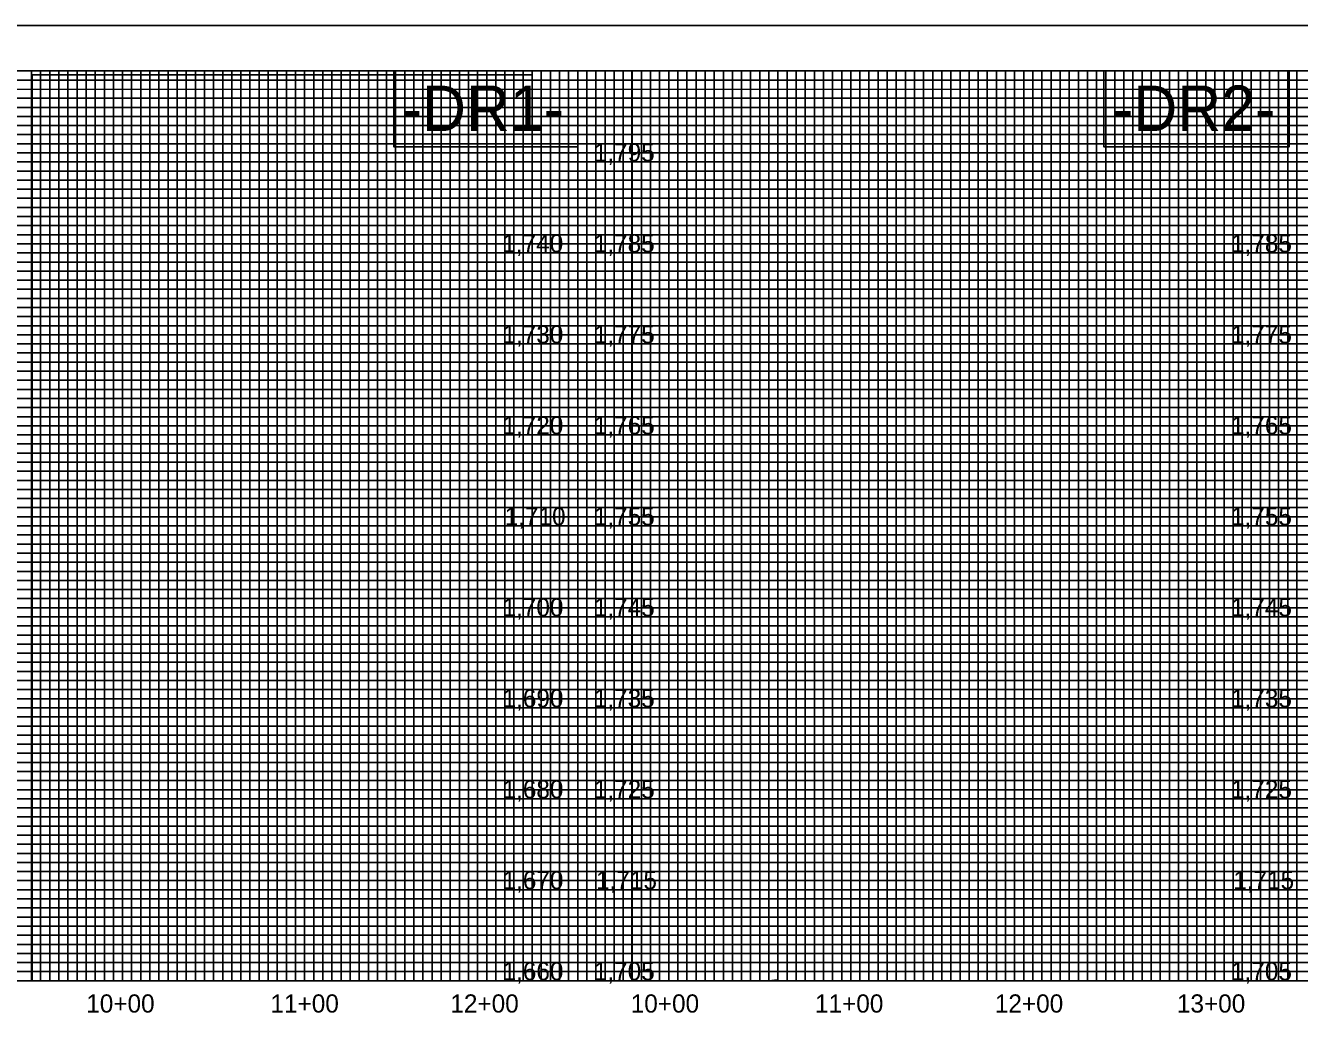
# Model space of a CAD drawing. Extents: x 505602 to 507286, y 483109 to 484209.
# Drawn here: x 506216 to 506916, y 483662 to 484209 of the extents above; entities that cross this region are included whole.
import ezdxf

# ---------------------------------------------------------------- set-up
doc = ezdxf.new("R2010")
doc.units = 0
for name, color, linetype in [('Exist Vertical Profile Vertical Axis Label', 7, 'Continuous'), ('Old_Level_1', 7, 'Continuous'), ('Prop Grid Mask', 7, 'Continuous'), ('Sheet Layout Profile Border Port 1', 7, 'Continuous'), ('Sheet Layout Profile Border Port 2', 7, 'Continuous'), ('Sheet Plot Border Outside CELL', 7, 'Continuous'), ('Sheet Profile CELL', 7, 'Continuous'), ('Sheet Profile Grid Major CELL', 7, 'Continuous'), ('Sheet Profile Grid Middle CELL', 7, 'Continuous'), ('Sheet Profile Grid Minor CELL', 7, 'Continuous')]:
    doc.layers.add(name, color=color, linetype=linetype)

msp = doc.modelspace()

# ---------------------------------------------------------------- linework, layer by layer
at = {"layer": 'Prop Grid Mask'}
for points in [[(506519.08, 484183.71), (506418.09, 484183.71), (506418.09, 484142), (506519.08, 484142)], [(506909.78, 484183.71), (506808.15, 484183.71), (506808.15, 484142), (506909.78, 484142)]]:
    msp.add_lwpolyline(points, close=True, dxfattribs=at)
at = {"layer": 'Sheet Layout Profile Border Port 1'}
msp.add_lwpolyline([(506219.48, 484181.62), (506494.08, 484181.62), (506494.08, 483683.71), (506219.48, 483683.71)], close=True, dxfattribs=at)
at = {"layer": 'Sheet Layout Profile Border Port 2'}
for points in [[(506519.08, 484183.71), (506869.08, 484183.71), (506869.08, 483683.71), (506519.08, 483683.71)], [(506548.8, 484183.71), (506869.08, 484183.71), (506869.08, 483683.71), (506548.8, 483683.71)]]:
    msp.add_lwpolyline(points, close=True, dxfattribs=at)
at = {"layer": 'Sheet Plot Border Outside CELL'}
msp.add_lwpolyline([(505602.08, 483108.71), (507286.08, 483108.71), (507286.08, 484208.71), (505602.08, 484208.71)], close=True, dxfattribs=at)
at = {"layer": 'Sheet Profile CELL'}
for p, q in [((506519.08, 483683.71), (506519.08, 484183.71)), ((505769.08, 483683.71), (507269.08, 483683.71))]:
    msp.add_line(p, q, dxfattribs=at)
msp.add_lwpolyline([(507269.08, 484183.71), (505769.08, 484183.71), (505769.08, 483133.71), (507269.08, 483133.71)], close=True, dxfattribs=at)
at = {"layer": 'Sheet Profile Grid Major CELL'}
for points in [[(506169.08, 484183.71), (506219.08, 484183.71), (506219.08, 483683.71), (506269.08, 483683.71), (506269.08, 484183.71), (506319.08, 484183.71), (506319.08, 483683.71), (506369.08, 483683.71), (506369.08, 484183.71), (506419.08, 484183.71), (506419.08, 483683.71), (506469.08, 483683.71), (506469.08, 484183.71), (506519.08, 484183.71), (506519.08, 483683.71), (506569.08, 483683.71), (506569.08, 484183.71), (506619.08, 484183.71), (506619.08, 483683.71), (506669.08, 483683.71), (506669.08, 484183.71), (506719.08, 484183.71), (506719.08, 483683.71), (506769.08, 483683.71), (506769.08, 484183.71), (506819.08, 484183.71), (506819.08, 483683.71), (506869.08, 483683.71), (506869.08, 484183.71), (506919.08, 484183.71)], [(505769.08, 484133.71), (507069.08, 484133.71)], [(507069.08, 484083.71), (505769.08, 484083.71), (505769.08, 484033.71), (507069.08, 484033.71)], [(507269.08, 483983.71), (505769.08, 483983.71), (505769.08, 483933.71), (507269.08, 483933.71)], [(507269.08, 483883.71), (505769.08, 483883.71), (505769.08, 483833.71), (507269.08, 483833.71)], [(507269.08, 483783.71), (505769.08, 483783.71), (505769.08, 483783.71), (505769.08, 483733.71), (507269.08, 483733.71)]]:
    msp.add_lwpolyline(points, dxfattribs=at)
at = {"layer": 'Sheet Profile Grid Middle CELL'}
msp.add_line((505769.08, 484158.71), (507069.03, 484158.71), dxfattribs=at)
msp.add_line((505769.08, 484158.71), (507069.03, 484158.71), dxfattribs=at)
for points in [[(506194.08, 484183.71), (506244.08, 484183.71), (506244.08, 483683.71), (506294.08, 483683.71), (506294.08, 484183.71), (506344.08, 484183.71), (506344.08, 483683.71), (506394.08, 483683.71), (506394.08, 483683.71), (506394.08, 484183.71), (506444.08, 484183.71), (506444.08, 483683.71), (506494.08, 483683.71), (506494.08, 484183.71), (506544.08, 484183.71), (506544.08, 483683.71), (506594.08, 483683.71), (506594.08, 484183.71), (506644.08, 484183.71), (506644.08, 483683.71), (506694.08, 483683.71), (506694.08, 484183.71), (506744.08, 484183.71), (506744.08, 483683.71), (506794.08, 483683.71), (506794.08, 484183.71), (506844.08, 484183.71), (506844.08, 483683.71), (506894.08, 483683.71), (506894.08, 484183.71), (506944.08, 484183.71)], [(507069.08, 484108.71), (505769.08, 484108.71), (505769.08, 484058.71), (507069.08, 484058.71)], [(507269.08, 484008.71), (505769.08, 484008.71), (505769.08, 483958.71), (507094.08, 483958.71)], [(507269.08, 483908.71), (505769.08, 483908.71), (505769.08, 483858.71), (507269.08, 483858.71)], [(507269.08, 483808.71), (505769.08, 483808.71), (505769.08, 483758.71), (507269.08, 483758.71)], [(507269.08, 483708.71), (505769.08, 483708.71)]]:
    msp.add_lwpolyline(points, dxfattribs=at)
at = {"layer": 'Sheet Profile Grid Minor CELL'}
for p, q in [((505819.08, 484178.71), (507069.08, 484178.71)), ((507069.08, 484173.71), (505819.08, 484173.36)), ((505819.08, 484168.71), (507069.08, 484168.71)), ((507069.03, 484048.71), (505819.08, 484048.71)), ((507069.08, 484043.71), (505819.08, 484043.71)), ((507069.08, 484038.71), (505819.08, 484038.71)), ((505819.08, 484028.71), (507069.08, 484028.71)), ((507069.08, 484023.71), (505819.08, 484023.71)), ((505819.08, 484018.71), (507219.08, 484018.71)), ((507219.08, 483998.71), (505819.08, 483998.71)), ((505819.08, 483993.71), (507219.08, 483993.71)), ((507219.08, 483973.71), (505819.08, 483973.71)), ((505819.08, 483968.71), (507219.08, 483968.71)), ((507219.08, 483948.71), (505819.08, 483948.71)), ((505819.08, 483943.71), (507219.08, 483943.71)), ((507219.08, 483938.71), (505819.08, 483938.71)), ((505819.08, 483928.71), (507219.08, 483928.71)), ((507219.08, 483923.71), (505819.08, 483923.71)), ((505819.08, 483918.71), (507219.08, 483918.71)), ((507219.08, 483913.71), (505819.08, 483913.71)), ((505819.08, 483903.71), (507219.08, 483903.71)), ((507219.08, 483898.71), (505819.08, 483898.71)), ((505819.08, 483893.71), (507219.08, 483893.71)), ((507219.08, 483888.71), (505819.08, 483888.71)), ((505819.08, 483878.71), (507219.08, 483878.71)), ((507219.08, 483873.71), (505819.08, 483873.71)), ((505819.08, 483868.71), (507219.08, 483868.71)), ((507219.08, 483863.71), (505819.08, 483863.71)), ((505819.08, 483853.71), (507219.08, 483853.71)), ((507219.08, 483848.71), (505819.08, 483848.71)), ((505819.08, 483843.71), (507219.08, 483843.71)), ((507219.08, 483838.71), (505819.08, 483838.71)), ((505819.08, 483828.71), (507219.08, 483828.71)), ((507219.08, 483823.71), (505819.08, 483823.71)), ((505819.08, 483818.71), (507219.08, 483818.71)), ((507219.08, 483813.71), (505819.08, 483813.71)), ((505819.08, 483803.71), (507219.08, 483803.71)), ((507219.08, 483798.71), (505819.08, 483798.71)), ((507219.08, 483793.71), (505819.08, 483793.71)), ((507219.08, 483788.71), (505819.08, 483788.71)), ((505819.08, 483778.71), (507219.08, 483778.71)), ((507219.08, 483773.71), (505819.08, 483773.71)), ((505819.08, 483768.71), (507219.08, 483768.71)), ((507219.08, 483763.71), (505819.08, 483763.71)), ((505819.08, 483753.71), (507219.08, 483753.71)), ((507219.08, 483748.71), (505819.08, 483748.71)), ((505819.08, 483743.71), (507219.08, 483743.71)), ((507219.08, 483738.71), (505819.08, 483738.71)), ((505819.08, 483728.71), (507219.08, 483728.71)), ((507219.08, 483723.71), (505819.08, 483723.71)), ((505819.08, 483718.71), (507219.08, 483718.71)), ((507219.08, 483713.71), (505819.08, 483713.71)), ((505819.08, 483703.71), (507219.08, 483703.71)), ((507219.08, 483698.71), (505819.08, 483698.71)), ((505819.08, 483693.71), (507219.08, 483693.71))]:
    msp.add_line(p, q, dxfattribs=at)
for points in [[(506214.08, 484183.71), (506224.08, 484183.71), (506224.08, 483683.71), (506229.08, 483683.71), (506229.08, 484183.71), (506234.08, 484183.71), (506234.08, 483683.71), (506239.08, 483683.71), (506239.08, 484183.71), (506249.08, 484183.71), (506249.08, 483683.71), (506254.08, 483683.71), (506254.08, 484183.71), (506259.08, 484183.71), (506259.08, 483683.71), (506264.08, 483683.71), (506264.08, 484183.71), (506274.08, 484183.71), (506274.08, 483683.71), (506279.08, 483683.71), (506279.08, 484183.71), (506284.08, 484183.71), (506284.08, 483683.71), (506289.08, 483683.71), (506289.08, 484183.71), (506299.08, 484183.71), (506299.08, 483683.71), (506304.08, 483683.71), (506304.08, 484183.71), (506309.08, 484183.71), (506309.08, 483683.71), (506314.08, 483683.71), (506314.08, 484183.71), (506324.08, 484183.71), (506324.08, 483683.71), (506329.08, 483683.71), (506329.08, 484183.71), (506334.08, 484183.71), (506334.08, 483683.71), (506339.08, 483683.71), (506339.08, 484183.71), (506349.08, 484183.71)], [(506349.08, 484183.71), (506349.08, 483683.71), (506354.08, 483683.71), (506354.08, 484183.71), (506359.08, 484183.71), (506359.08, 483683.71), (506364.08, 483683.71), (506364.08, 484183.71), (506374.08, 484183.71), (506374.08, 483683.71), (506379.08, 483683.71), (506379.08, 484183.71), (506384.08, 484183.71), (506384.08, 483683.71), (506389.08, 483683.71), (506389.08, 484183.71), (506399.08, 484183.71), (506399.08, 483683.71), (506404.08, 483683.71), (506404.08, 484183.71), (506409.08, 484183.71), (506409.08, 483683.71), (506414.08, 483683.71), (506414.08, 484183.71), (506424.08, 484183.71), (506424.08, 483683.71), (506429.08, 483683.71), (506429.08, 484183.71), (506434.08, 484183.71), (506434.08, 483683.71), (506439.08, 483683.71), (506439.08, 484183.71), (506449.08, 484183.71), (506449.08, 483683.71), (506454.08, 483683.71), (506454.08, 484183.71), (506459.08, 484183.71), (506459.08, 483683.71), (506464.08, 483683.71), (506464.08, 484183.71), (506474.08, 484183.71), (506474.08, 483683.71), (506474.08, 483683.71), (506479.08, 483683.71), (506479.08, 484183.71), (506484.08, 484183.71), (506484.08, 483683.71), (506489.08, 483683.71), (506489.08, 484183.71), (506499.08, 484183.71), (506499.08, 483683.71), (506504.08, 483683.71), (506504.08, 484183.71), (506509.08, 484183.71), (506509.08, 483683.71), (506514.08, 483683.71), (506514.08, 484183.71), (506524.08, 484183.71), (506524.08, 483683.71), (506529.08, 483683.71), (506529.08, 484183.71), (506534.08, 484183.71), (506534.08, 483683.71), (506539.08, 483683.71), (506539.08, 484183.71), (506549.08, 484183.71), (506549.08, 483683.71), (506554.08, 483683.71), (506554.08, 484183.71), (506559.08, 484183.71), (506559.08, 483683.71), (506564.08, 483683.71), (506564.08, 484183.71), (506574.08, 484183.71), (506574.08, 483683.71), (506579.08, 483683.71), (506579.08, 484183.71), (506584.08, 484183.71), (506584.08, 483683.71), (506589.08, 483683.71), (506589.08, 484183.71), (506599.08, 484183.71), (506599.08, 483683.71), (506604.08, 483683.71), (506604.08, 484183.71), (506609.08, 484183.71), (506609.08, 483683.71), (506614.08, 483683.71), (506614.08, 484183.71), (506624.08, 484183.71), (506624.08, 483683.71), (506628.78, 483684.26), (506629.08, 483683.71), (506629.08, 484183.71), (506634.08, 484183.71), (506634.08, 483683.71), (506639.08, 483683.71), (506639.08, 484183.71), (506649.08, 484183.71), (506649.08, 483683.71), (506654.08, 483683.71)], [(506654.08, 483683.71), (506654.08, 484183.71), (506659.08, 484183.71), (506659.08, 483683.71), (506664.08, 483683.71), (506664.08, 484183.71), (506674.08, 484183.71), (506674.08, 483683.71), (506679.08, 483683.71), (506679.08, 484183.71), (506684.08, 484183.71), (506684.08, 483683.71), (506689.08, 483683.71), (506689.08, 484183.71), (506699.08, 484183.71), (506699.08, 483683.71), (506704.08, 483683.71), (506704.08, 484183.71), (506709.08, 484183.71), (506709.08, 483683.71), (506714.08, 483683.71), (506714.08, 484183.71), (506724.08, 484183.71), (506724.08, 483683.71), (506729.08, 483683.71), (506729.08, 484183.71), (506734.08, 484183.71), (506734.08, 483683.71), (506739.08, 483683.71), (506739.08, 484183.71), (506749.08, 484183.71), (506749.08, 483683.71), (506754.08, 483683.71), (506754.08, 484183.71), (506759.08, 484183.71), (506759.08, 483683.71), (506764.08, 483683.71), (506764.08, 484183.71), (506774.08, 484183.71), (506774.08, 483683.71), (506779.08, 483683.71), (506779.08, 484183.71), (506784.08, 484183.71), (506784.08, 483683.71), (506789.08, 483683.71), (506789.08, 484183.71), (506799.08, 484183.71), (506799.08, 483683.71), (506804.08, 483683.71), (506804.08, 484183.71), (506809.08, 484183.71), (506809.08, 483683.71), (506814.08, 483683.71), (506814.08, 484183.71), (506824.08, 484183.71), (506824.08, 483683.71), (506829.08, 483683.71), (506829.08, 484183.71), (506834.08, 484183.71), (506834.08, 483683.71), (506839.08, 483683.71), (506839.08, 484183.71), (506849.08, 484183.71), (506849.08, 483683.71), (506854.08, 483683.71), (506854.08, 484183.71), (506859.08, 484183.71), (506859.08, 483683.71), (506864.08, 483683.71), (506864.08, 484183.71), (506874.08, 484183.71), (506874.08, 483683.71), (506879.08, 483683.71), (506879.08, 484183.71), (506884.08, 484183.71), (506884.08, 483683.71), (506889.08, 483683.71), (506889.08, 484183.71), (506899.08, 484183.71), (506899.08, 483683.71), (506904.08, 483683.71), (506904.08, 484183.71), (506909.08, 484183.71), (506909.08, 483683.71), (506914.08, 483683.71), (506914.08, 484183.71), (506924.08, 484183.71)], [(507069.08, 484163.71), (505819.08, 484163.71), (505819.08, 484153.71), (507069.08, 484153.71)], [(507069.03, 484148.71), (505819.08, 484148.71), (505819.08, 484143.71), (507069.08, 484143.71)], [(507069.08, 484138.71), (505819.08, 484138.71), (505819.08, 484128.71), (507069.08, 484128.71)], [(507069.08, 484123.71), (505819.08, 484123.71), (505819.08, 484118.71), (507069.08, 484118.71)], [(507069.08, 484113.71), (505819.08, 484113.71), (505819.08, 484103.71), (507069.08, 484103.71)], [(507069.08, 484098.71), (505819.08, 484098.71), (505819.08, 484093.71), (507069.08, 484093.71)], [(507069.08, 484088.71), (505819.08, 484088.71), (505819.08, 484078.71), (507069.08, 484078.71)], [(507069.08, 484073.61), (505819.18, 484073.61), (505819.18, 484068.71), (507069.08, 484068.71)], [(507069.08, 484063.71), (505819.08, 484063.71), (505819.08, 484053.71), (507069.08, 484053.71)], [(507219.08, 484013.71), (505819.08, 484013.71), (505819.08, 484003.71), (507219.08, 484003.71)], [(507219.08, 483988.71), (505819.08, 483988.71), (505819.08, 483978.71), (507219.08, 483978.71)], [(507219.08, 483963.71), (505819.08, 483963.71), (505819.08, 483953.71), (507219.08, 483953.71)], [(507219.08, 483688.71), (505819.08, 483688.71)]]:
    msp.add_lwpolyline(points, dxfattribs=at)

# ---------------------------------------------------------------- texts
at = {"layer": 'Exist Vertical Profile Vertical Axis Label'}
for s, p in [('1,795', (506527.93, 484133.96)), ('1,740', (506477.69, 484083.96)), ('1,785', (506527.93, 484083.96)), ('1,785', (506877.93, 484083.96)), ('1,730', (506477.73, 484033.96)), ('1,775', (506527.93, 484033.96)), ('1,775', (506877.93, 484033.96)), ('1,720', (506477.73, 483983.96)), ('1,765', (506527.93, 483983.96)), ('1,765', (506877.93, 483983.96)), ('1,710', (506478.97, 483933.96)), ('1,755', (506527.93, 483933.96)), ('1,755', (506877.93, 483933.96)), ('1,700', (506477.78, 483883.96)), ('1,745', (506527.93, 483883.96)), ('1,745', (506877.93, 483883.96)), ('1,690', (506477.78, 483833.96)), ('1,735', (506527.93, 483833.96)), ('1,735', (506877.93, 483833.96)), ('1,680', (506477.78, 483783.96)), ('1,725', (506527.93, 483783.96)), ('1,725', (506877.93, 483783.96)), ('1,670', (506477.78, 483733.96)), ('1,715', (506529.13, 483733.96)), ('1,715', (506879.13, 483733.96)), ('1,660', (506477.78, 483683.96)), ('1,705', (506527.93, 483683.96)), ('1,705', (506877.93, 483683.96)), ('10+00', (506249.13, 483666.21)), ('11+00', (506350.33, 483666.21)), ('12+00', (506449.13, 483666.21)), ('10+00', (506548.21, 483666.21)), ('11+00', (506649.41, 483666.21)), ('12+00', (506748.21, 483666.21)), ('13+00', (506848.21, 483666.21))]:
    msp.add_text(s, height=10, dxfattribs=at).set_placement(p)
at = {"layer": 'Old_Level_1'}
for s, p in [('-DR1-', (506422.42, 484150.68)), ('-DR2-', (506813.12, 484150.68))]:
    msp.add_text(s, height=25, dxfattribs=at).set_placement(p)

doc.saveas('drawing.dxf')
